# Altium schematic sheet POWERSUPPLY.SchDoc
size A4; PageSetup: Record=PageOptions|CenterHorizontal=True|CenterVertical=True|PrintScale=0.97|XCorrection=1.00|YCorrection=1.00|PrintKind=0|BorderSize=5000000|LeftOffset=5|BottomOffset=0|Orientation=1|PaperLength=1000|PaperWidth=1000|Scale=100|PaperSource=7|PrintQuality=-4|MediaType=1|DitherType=10|PaperKind=A4|PrintScaleMode=1
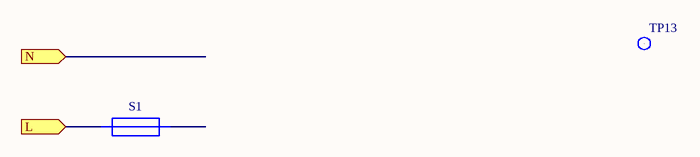
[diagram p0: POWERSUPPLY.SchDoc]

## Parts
S1  SICHERUNGSHALTER_MIRA  (value not drawn)
TP13  LP10  (value not drawn)  (no BOM)

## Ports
L, N

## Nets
L: S1.1 ; port L

Not connected (* = marked no-connect by the designer): S1 4; TP13 1

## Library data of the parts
S1 = SICHERUNGSHALTER_MIRA: PART DESCE: FUSEHOLDER; Geometry.Height: 14.0mm; SUPP.#1: MIRA; SUPP.ART.#1: 7851/6
TP13 = LP10: PART DESCE: SOLDER PIN 0,9 mm; MFG.#1: ETTINGER; GR: TP; SUPP.#1: BUERKLIN; SUPP.ART.#1: 12 H 6158; PCB DECAL: TP01X0Y0B39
